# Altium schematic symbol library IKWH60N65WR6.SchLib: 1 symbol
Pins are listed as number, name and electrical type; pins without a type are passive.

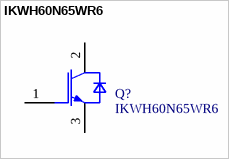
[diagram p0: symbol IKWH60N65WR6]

## IKWH60N65WR6
designator Q?
Isolated-Gate Bipolar Transistor (IGBT), N-Channel, Depletion, Body Diode, Pin 1 Gate, 2 Collector, 3 Emitter, 3 Pins; Manufacturer: Infineon Technologies
pins: 1 GATE, 2 COLLECTOR, 3 EMITTER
